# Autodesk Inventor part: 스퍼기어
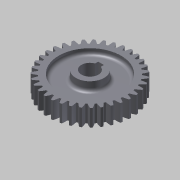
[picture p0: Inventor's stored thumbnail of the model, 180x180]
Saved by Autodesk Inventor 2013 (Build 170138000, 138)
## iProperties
Created: 2013-08
Part Number: 스퍼기어
Material: 강
Document SubType Name: Modeling
Designer: 한국산업디자인학원
Categories: <?xml version="1.0" encoding="UTF-16"?> <MemberInstance><Categories><FamilyTemplate><FamilyTemplateParameter ValueType="xs:double" Id="1" ObjectReferenceKey="da
Density: 1 g/cm^3
CustomPartVersion: 1
Author: 한국산업디자인학원
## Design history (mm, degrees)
sketch "Sketch1"
  geometry: C1 r 37 at (0, 0)
  constraints: 1 centre point
  dimensions: "d0" = 74 diameter of C1 (= da_da)
extrude "Extrusion1" new body sketch "Sketch1" distance "d1" = 15 (= da_b); taper "d2" = 0 deg
workplane "Work Plane2"
feature "피치 지름" dims "d4" = 10, "d5" = 0
workplane "Work Plane8"
workplane "Work Plane9"
feature "스퍼 기어" dims "da_b" = 15, "da_d" = 70, "da_aw" = 70, "da_da" = 74, "da_df" = 65, "da_dw" = 70, angle "da_beta" = 0 deg, "da_lefttooth" = 0, "da_righttooth" = 0
sketch "스케치3"
  geometry: L1 (0, 0)-(0, 15); L2 (0, 0)-(12.5, 0); L3 (12.5, 0)-(12.5, 5); L4 (12.5, 5)-(27.5, 5); L5 (27.5, 5)-(27.5, 0); L6 (27.5, 0)-(32.75, 0); L7 (32.75, 0)-(32.75, 15); L8 (32.75, 15)-(27.5, 15); L9 (27.5, 15)-(27.5, 10); L10 (27.5, 10)-(12.5, 10); L11 (12.5, 10)-(12.5, 15); L12 (12.5, 15)-(0, 15); L13 (12.5, 10)-(0, 10); L14 (12.5, 5)-(0, 5); L15 (27.5, 15)-(12.5, 15); L16 (12.5, 10)-(12.5, 5); L17 (27.5, 10)-(27.5, 5); L18 (27.5, 0)-(12.5, 0); L19 (12.5, 15)-(0, 15); L20 (0, 0)-(12.5, 0); L21 (12.5, 10)-(0, 10); L22 (12.5, 5)-(0, 5)
  constraints: 44 end point, 8 parallel, 5 collinear, 5 perpendicular, 4 equal length, 2 point on line, 1 vertical
  dimensions: "d49" = 55 diameter of L9 L1; "d51" = 15 distance of L1.start L1.end; "d52" = 5 distance of L3.end L2.end; "d53" = 25 diameter of L2.end L1; "d54" = 65.5 diameter of L7 L1; "d55" = 15 distance of L7.end L6.end
revolve "회전1" sketch "스케치3" stored, may be unused: angle "d56" = 90 deg
sketch "스케치4"
  geometry: C1 r 12.5 at (0, 0) reference; C2 r 12.5 at (0, 0)
  constraints: 1 centre point, 1 coincident, 1 concentric
extrude "돌출2" join sketch "스케치4" distance "d57" = 13; taper "d58" = 0 deg
sketch "스케치5"
  geometry: C1 r 12.5 at (0, 0) reference; C2 r 12.5 at (0, 0)
  constraints: 1 centre point, 1 coincident, 1 concentric
extrude "돌출3" join sketch "스케치5" distance "d59" = 3; taper "d60" = 0 deg
sketch "스케치6"
  geometry: L1 (-2.5, 9.8)-(2.5, 9.8); L2 (2.5, 9.8)-(2.5, 7.071); L3 (-2.5, 9.8)-(-2.5, 7.071); C1 r 12.5 at (0, 0) reference; A1 r 7.5 centre (0, 0) between (-2.5, 7.071) and (2.5, 7.071); 1 further point
  constraints: 6 end point, 2 point on circle, 1 centre point, 1 coincident, 1 horizontal, 1 midpoint, 1 parallel, 1 perpendicular, 1 vertical alignment
  dimensions: "d61" = 5 distance of L1.start L1.end; "d63" = 15 diameter of A1; "d64" = 9.8 distance of C1.centre point (0, 9.8)
extrude "돌출4" cut sketch "스케치6" stored distance "d65" = 3; taper "d66" = 0 deg
fillet "모깎기1" dims "d67" = 3
body "Solid1"
sketch "Sketch2"
  geometry: C1 r 37 at (0, 0) reference; C2 r 35 at (0, 0)
  constraints: 1 centre point, 1 coincident
  dimensions: "d3" = 70 diameter of C2 (= da_dw)
body "Srf1"
other parameters: "d17" = 0, "d34" = 0.8976 (computed from da_z), "d39" = 0, "d41" = 0, "d47" = 0, "d48" = 0
